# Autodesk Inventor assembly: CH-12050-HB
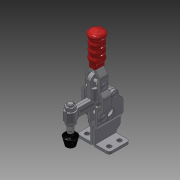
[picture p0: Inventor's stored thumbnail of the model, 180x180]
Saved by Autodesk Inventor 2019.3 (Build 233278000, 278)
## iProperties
Company: Î¢ÈíÖÐ¹ú
Created: 2012-07
Part Number: CH-12050-HB
Material: Ogólny
Description: STEP AP203
Document SubType Name: Assembly
Designer: CADENGINEERING4
Stock Number: DOCISK PIONOWY
Sending System: SolidWorks 2010
Preprocessor: SwSTEP 2.0
Title: CH-12050-HB.STEP
Author: Î¢ÈíÓÃ»§
Revision Number: ÈÎºÎ
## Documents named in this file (10)
- D:\Vault_2016\Projekty\Clamptek\STRONA\Vertical toggle clamp\CH-12050-HB\CH-12050-HB_ZAMKNIETY.iam
- D:\Vault_2016\Projekty\Clamptek\STRONA\Vertical toggle clamp\CH-12050-HB\CH-12050-07.ipt
- D:\Vault_2016\Projekty\Clamptek\STRONA\Vertical toggle clamp\CH-12050-HB\CH-FC-14134 Nut.ipt
- D:\Vault_2016\Projekty\Clamptek\STRONA\Vertical toggle clamp\CH-12050-HB\CH-12050-06.ipt
- D:\Vault_2016\Projekty\Clamptek\STRONA\Vertical toggle clamp\CH-12050-HB\CH-12050-HB-02 FIXED SPINDLE.ipt
- D:\Vault_2016\Projekty\Clamptek\STRONA\Vertical toggle clamp\CH-12050-HB\CH-12050-HB-01 FLANGED BASE.ipt
- D:\Vault_2016\Projekty\Clamptek\STRONA\Vertical toggle clamp\CH-12050-HB\CH-FC-14134 SPINDLE SUPPLIED.ipt
- D:\Vault_2016\Projekty\Clamptek\STRONA\Vertical toggle clamp\CH-12050-HB\CH-12050-04 CONNECTING-PLATE.ipt
- D:\Vault_2016\Projekty\Clamptek\STRONA\Vertical toggle clamp\CH-12050-HB\CH-12050-03 STRAIGHT HANDLE.ipt
- D:\Vault_2016\Projekty\Clamptek\STRONA\Vertical toggle clamp\CH-12050-HB\CH-12050-05.ipt
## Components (13 placed, 13 different names)
1. CH-12050-07_1 — Zestawiające:24
2. CH-FC-14134 Nut_2
3. CH-12050-06_3
4. CH-FC-14134 Nut_4
5. CH-12050-07_5
6. CH-12050-HB-02 FIXED SPINDLE_6
7. CH-12050-HB-01 FLANGED BASE_7
8. CH-FC-14134 SPINDLE SUPPLIED_8
9. CH-12050-04 CONNECTING-PLATE_9
10. CH-12050-06_10
11. CH-12050-03 STRAIGHT HANDLE_11
12. CH-12050-05_12
13. CH-12050-07:3 — Zestawiające:24
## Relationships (1: Mate 1)
- Zestawiające:24 [Mate]: CH-12050-07_1 ↔ CH-12050-07:3
